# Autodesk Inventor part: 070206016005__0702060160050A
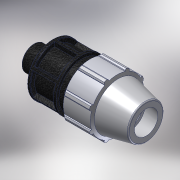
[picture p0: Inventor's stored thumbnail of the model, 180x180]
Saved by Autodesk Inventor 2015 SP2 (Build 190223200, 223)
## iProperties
Created: 2017-02
Part Number: 070206016005__0702060160050A
Material: PVC-Piping
Description: PLASSON MALE ADAPTOR 16-1/2"
Document SubType Name: Modeling
Designer: KIM
Mass: 92.6774 g
Surface Area: 199.44 cm^2
Volume: 66.1981 cm^3
Density: 1.4 g/cm^3
Appearance: PTFE
Author: KIM
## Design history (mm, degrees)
derived "07020.ipt"
feature "Solid1::07020.ipt"
tag "TaggingFeature1"
body "Solid1"
other parameters: "d2" = 16, "d4" = 11.28571, "d5" = 19.75, "d7" = 39, "d8" = 29.25, "d9" = 11.28571, "d11" = 2.25714, "d12" = 31.2, "d13" = 120 deg, "d14" = 24, "d15" = 12 deg, "d16" = 35.1, "d18" = 0.8, "d19" = 35 deg, "d20" = 17.5 deg, "d21" = 36.27, "d23" = 0, "d25" = 360 deg, "d27" = 0.78, "d34" = 1.95, "d36" = 0, "d42" = 19.75, "d43" = 1.17, "d46" = 0.48, "d49" = 59, "d51" = 79, "d52" = 16, "d53" = 0.32, "d55" = 360 deg, "d57" = 20.955, "d58" = 14.6685, "d59" = 15.8, "d_" = 16, "E_" = 39, "H_" = 79, "l_" = 59, "l_2" = 16, "R_" = 20.955
